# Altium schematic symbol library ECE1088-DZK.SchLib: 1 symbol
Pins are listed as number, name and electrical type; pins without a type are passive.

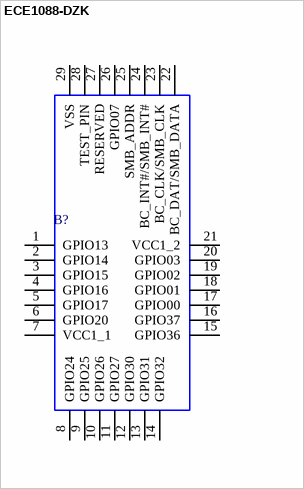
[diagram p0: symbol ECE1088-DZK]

## ECE1088-DZK
designator B?
Interface - I/O Expanders GPIO EXPANSION SMbus; Manufacturer_Name: Microchip; Geometry.Height: 1mm
footprint QFN50P500X500X100-29N-D
pins: 1 GPIO13, 2 GPIO14, 3 GPIO15, 4 GPIO16, 5 GPIO17, 6 GPIO20, 7 VCC1_1, 8 GPIO24, 9 GPIO25, 10 GPIO26, 11 GPIO27, 12 GPIO30, 13 GPIO31, 14 GPIO32, 15 GPIO36, 16 GPIO37, 17 GPIO00, 18 GPIO01, 19 GPIO02, 20 GPIO03, 21 VCC1_2, 22 BC_DAT/SMB_DATA, 23 BC_CLK/SMB_CLK, 24 BC_INT#/SMB_INT#, 25 SMB_ADDR, 26 GPIO07, 27 RESERVED, 28 TEST_PIN, 29 VSS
